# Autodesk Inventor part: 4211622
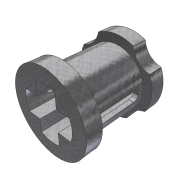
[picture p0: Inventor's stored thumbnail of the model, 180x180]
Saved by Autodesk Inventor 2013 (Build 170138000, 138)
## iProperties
Created: 2013-03
Part Number: 4211622
Material: Generic
Document SubType Name: Modeling
Designer: perblt
Density: 1 g/cm^3
Translation Standard: STEP AP203
FileName: 4211622
PreProcessor: PRO/ENGINEER BY PARAMETRIC TECHNOLOGY CORPORATION, 2010370
PostProcessor: Build: 138, Release: 2013 RTM - Date: Thu 03/01/2012
Sent Units: millimeter
Uncertainty: 0.0018004495971029998
Author: perblt
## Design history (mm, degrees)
node "42116221"
node "4211622"
node "Base1"
